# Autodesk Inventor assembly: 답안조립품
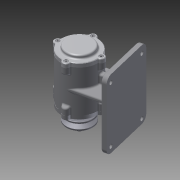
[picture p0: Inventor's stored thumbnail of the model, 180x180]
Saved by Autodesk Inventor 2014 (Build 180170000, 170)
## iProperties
Created: 2015-12
Part Number: 답안조립품
Document SubType Name: Assembly
Designer: user
Author: user
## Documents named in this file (11)
- C:\Users\user\Desktop\451208V1008\답안조립품.iam
- C:\Users\user\Desktop\451208V1008\본체.ipt
- C:\Users\user\Desktop\451208V1008\축.ipt
- C:\Users\user\Desktop\451208V1008\커버.ipt
- C:\Users\user\Desktop\451208V1008\커버2.ipt
- C:\Users\user\Desktop\451208V1008\오일실.ipt
- C:\Users\user\Desktop\451208V1008\베어링 6204.ipt
- C:\Users\user\Desktop\451208V1008\V-벨트풀리.ipt
- C:\Users\user\Desktop\451208V1008\너트 M12x1.25.ipt
- C:\Users\user\Desktop\451208V1008\키(4 x 4 x 12).ipt
- C:\Users\user\Desktop\451208V1008\볼트 M4 x 12.ipt
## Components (6 placed, 5 different names)
1. KS B 2804 D D - 20 32 8:1 — Mate:13, Mate:14
2. KS B 2023 6204 - 20 x 47 x 14:1 — Mate:5, Mate:6, Mate:7
3. KS B 2023 6204 - 20 x 47 x 14:2 — Mate:8, Mate:9
4. V-벨트풀리:1 — Mate:18, Mate:19, Mate:20, Angle:1, Mate:22
5. KS B 1012 클래스 1 일반 - 미터 M12x1.25:1 — Mate:21, Angle:1, Mate:22
6. KS B 1311 (I) 4 x 4 x 12:1 — Mate:15, Mate:16, Mate:17, Mate:19
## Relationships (16: Mate 15, Angle 1)
- Mate:5: KS B 2023 6204 - 20 x 47 x 14:1
- Mate:6: KS B 2023 6204 - 20 x 47 x 14:1
- Mate:7: KS B 2023 6204 - 20 x 47 x 14:1
- Mate:8: KS B 2023 6204 - 20 x 47 x 14:2
- Mate:9: KS B 2023 6204 - 20 x 47 x 14:2
- Mate:13: KS B 2804 D D - 20 32 8:1
- Mate:14: KS B 2804 D D - 20 32 8:1
- Mate:15: KS B 1311 (I) 4 x 4 x 12:1
- Mate:16: KS B 1311 (I) 4 x 4 x 12:1
- Mate:17: KS B 1311 (I) 4 x 4 x 12:1
- Mate:18: V-벨트풀리:1
- Mate:19: V-벨트풀리:1 ↔ KS B 1311 (I) 4 x 4 x 12:1
- Mate:20: V-벨트풀리:1
- Mate:21: KS B 1012 클래스 1 일반 - 미터 M12x1.25:1
- Angle:1: V-벨트풀리:1 ↔ KS B 1012 클래스 1 일반 - 미터 M12x1.25:1
- Mate:22: V-벨트풀리:1 ↔ KS B 1012 클래스 1 일반 - 미터 M12x1.25:1
